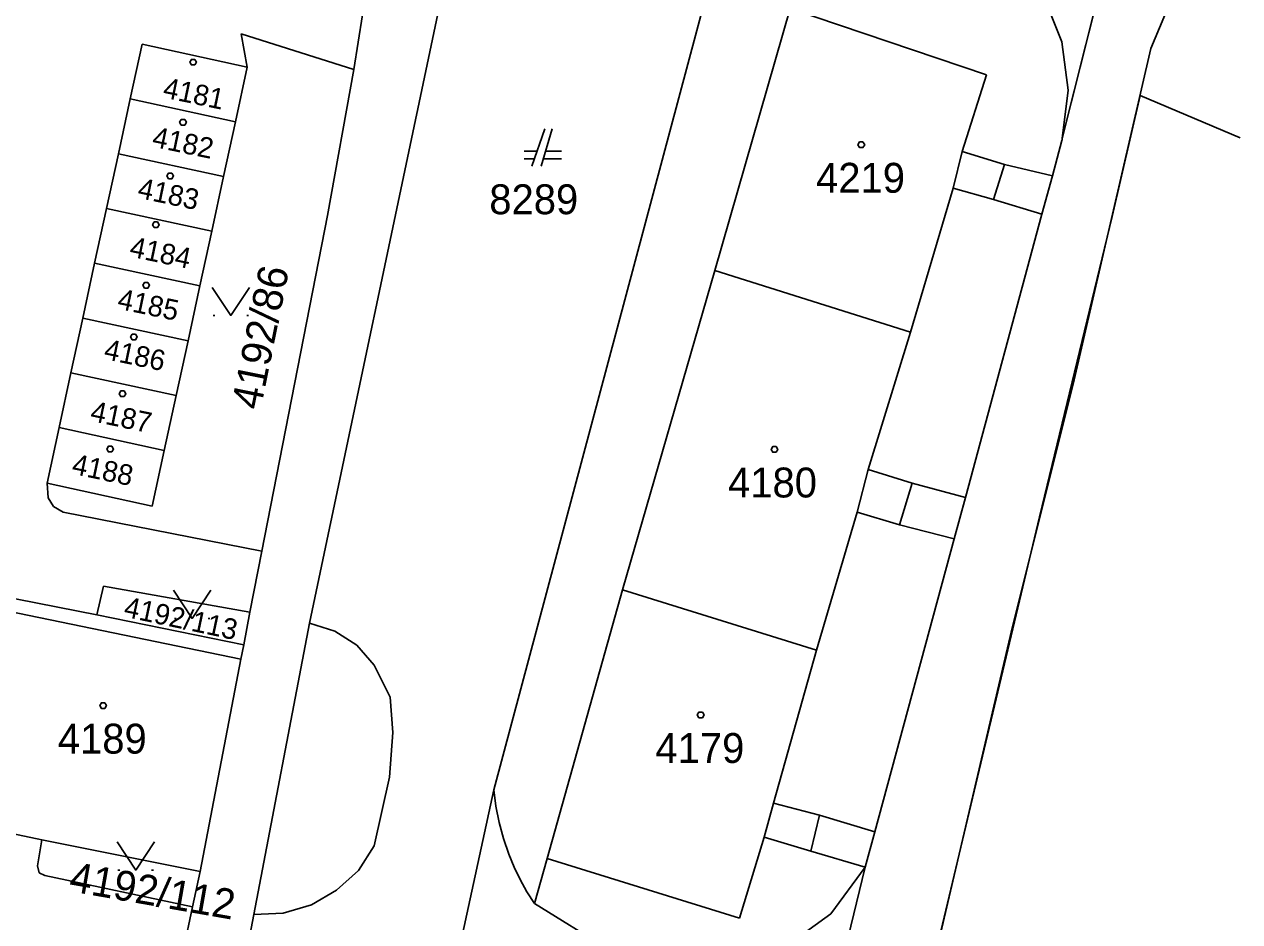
# Model space of a CAD drawing. Extents: x -263587 to -261993, y -1238795 to -1236748.
# Drawn here: x -262886.4 to -262821.3, y -1237709.3 to -1237661.2 of the extents above; entities that cross this region are included whole.
import ezdxf

# ---------------------------------------------------------------- set-up
doc = ezdxf.new("R2010")
doc.units = 0
doc.layers.add('Vrstva 1', color=7, linetype='Continuous')
doc.layers.add('Vrstva 2', color=7, linetype='Continuous')

msp = doc.modelspace()

# ---------------------------------------------------------------- linework, layer by layer
at = {"layer": 'Vrstva 1'}
for p, q in [((-262827.27, -1237653.08), (-262830.83, -1237667.35)), ((-262830.83, -1237667.35), (-262827.27, -1237653.08)), ((-262824.33, -1237658.31), (-262826.09, -1237662.53)), ((-262826.09, -1237662.53), (-262824.33, -1237658.31)), ((-262861.26, -1237702.2), (-262849.76, -1237659.19)), ((-262830.86, -1237662.17), (-262831.82, -1237659.75)), ((-262849.43, -1237674.41), (-262845.39, -1237660.38)), ((-262845.39, -1237660.38), (-262849.43, -1237674.41)), ((-262845.39, -1237660.38), (-262834.89, -1237663.94)), ((-262834.89, -1237663.94), (-262845.39, -1237660.38)), ((-262871.13, -1237693.29), (-262864.25, -1237660.67)), ((-262868.29, -1237660.73), (-262868.76, -1237663.65)), ((-262868.76, -1237663.65), (-262868.29, -1237660.73)), ((-262874.46, -1237663.52), (-262874.79, -1237661.74)), ((-262874.79, -1237661.74), (-262868.76, -1237663.65)), ((-262868.76, -1237663.65), (-262874.79, -1237661.74)), ((-262874.79, -1237661.74), (-262874.46, -1237663.52)), ((-262880.72, -1237665.23), (-262880.09, -1237662.3)), ((-262880.09, -1237662.3), (-262880.72, -1237665.23)), ((-262880.09, -1237662.3), (-262874.46, -1237663.52)), ((-262874.46, -1237663.52), (-262880.09, -1237662.3)), ((-262830.51, -1237664.76), (-262830.86, -1237662.17)), ((-262826.09, -1237662.53), (-262830.25, -1237680.5)), ((-262830.25, -1237680.5), (-262826.09, -1237662.53)), ((-262874.46, -1237663.52), (-262875.09, -1237666.45)), ((-262875.09, -1237666.45), (-262874.46, -1237663.52)), ((-262868.76, -1237663.65), (-262870.17, -1237671.47)), ((-262870.17, -1237671.47), (-262868.76, -1237663.65)), ((-262834.89, -1237663.94), (-262836.19, -1237668.04)), ((-262836.19, -1237668.04), (-262834.89, -1237663.94)), ((-262830.83, -1237667.35), (-262830.51, -1237664.76)), ((-262881.36, -1237668.16), (-262880.72, -1237665.23)), ((-262880.72, -1237665.23), (-262881.36, -1237668.16)), ((-262880.72, -1237665.23), (-262875.09, -1237666.45)), ((-262875.09, -1237666.45), (-262880.72, -1237665.23)), ((-262875.09, -1237666.45), (-262875.73, -1237669.38)), ((-262875.73, -1237669.38), (-262875.09, -1237666.45)), ((-262858.53, -1237666.83), (-262859.23, -1237668.83)), ((-262858.73, -1237668.83), (-262858.13, -1237666.83)), ((-262830.85, -1237667.46), (-262831.36, -1237669.34)), ((-262831.36, -1237669.34), (-262830.85, -1237667.46)), ((-262830.84, -1237667.41), (-262830.85, -1237667.46)), ((-262830.85, -1237667.46), (-262830.84, -1237667.41)), ((-262830.85, -1237667.46), (-262830.84, -1237667.41)), ((-262830.83, -1237667.35), (-262830.84, -1237667.41)), ((-262830.84, -1237667.41), (-262830.83, -1237667.35)), ((-262881.99, -1237671.09), (-262881.36, -1237668.16)), ((-262881.36, -1237668.16), (-262881.99, -1237671.09)), ((-262881.36, -1237668.16), (-262875.73, -1237669.38)), ((-262875.73, -1237669.38), (-262881.36, -1237668.16)), ((-262858.95, -1237668.03), (-262859.63, -1237668.03)), ((-262857.63, -1237668.03), (-262858.49, -1237668.03)), ((-262836.19, -1237668.04), (-262836.68, -1237670)), ((-262836.19, -1237668.04), (-262833.92, -1237668.73)), ((-262833.92, -1237668.73), (-262836.19, -1237668.04)), ((-262859.63, -1237668.43), (-262859.09, -1237668.43)), ((-262858.61, -1237668.43), (-262857.63, -1237668.43)), ((-262833.92, -1237668.73), (-262834.51, -1237670.62)), ((-262834.51, -1237670.62), (-262833.92, -1237668.73)), ((-262833.92, -1237668.73), (-262831.36, -1237669.34)), ((-262875.73, -1237669.38), (-262876.36, -1237672.31)), ((-262876.36, -1237672.31), (-262875.73, -1237669.38)), ((-262831.36, -1237669.34), (-262831.92, -1237671.4)), ((-262831.92, -1237671.4), (-262831.36, -1237669.34)), ((-262836.68, -1237670), (-262838.95, -1237677.71)), ((-262838.95, -1237677.71), (-262836.68, -1237670)), ((-262834.51, -1237670.62), (-262836.68, -1237670)), ((-262836.68, -1237670), (-262834.51, -1237670.62)), ((-262834.51, -1237670.62), (-262831.92, -1237671.4)), ((-262882.63, -1237674.02), (-262881.99, -1237671.09)), ((-262881.99, -1237671.09), (-262882.63, -1237674.02)), ((-262881.99, -1237671.09), (-262876.36, -1237672.31)), ((-262876.36, -1237672.31), (-262881.99, -1237671.09)), ((-262870.17, -1237671.47), (-262873.68, -1237689.44)), ((-262873.68, -1237689.44), (-262870.17, -1237671.47)), ((-262831.92, -1237671.4), (-262836.01, -1237686.56)), ((-262836.01, -1237686.56), (-262831.92, -1237671.4)), ((-262876.36, -1237672.31), (-262877, -1237675.24)), ((-262877, -1237675.24), (-262876.36, -1237672.31)), ((-262883.26, -1237676.96), (-262882.63, -1237674.02)), ((-262882.63, -1237674.02), (-262883.26, -1237676.96)), ((-262882.63, -1237674.02), (-262877, -1237675.24)), ((-262877, -1237675.24), (-262882.63, -1237674.02)), ((-262854.38, -1237691.5), (-262849.43, -1237674.41)), ((-262849.43, -1237674.41), (-262854.38, -1237691.5)), ((-262849.43, -1237674.41), (-262838.95, -1237677.71)), ((-262838.95, -1237677.71), (-262849.43, -1237674.41)), ((-262877, -1237675.24), (-262877.63, -1237678.18)), ((-262877.63, -1237678.18), (-262877, -1237675.24)), ((-262883.9, -1237679.89), (-262883.26, -1237676.96)), ((-262883.26, -1237676.96), (-262883.9, -1237679.89)), ((-262883.26, -1237676.96), (-262877.63, -1237678.18)), ((-262877.63, -1237678.18), (-262883.26, -1237676.96)), ((-262876.29, -1237676.82), (-262876.19, -1237676.82)), ((-262874.49, -1237676.82), (-262874.39, -1237676.82)), ((-262838.95, -1237677.71), (-262841.22, -1237685.07)), ((-262841.22, -1237685.07), (-262838.95, -1237677.71)), ((-262877.63, -1237678.18), (-262878.27, -1237681.11)), ((-262878.27, -1237681.11), (-262877.63, -1237678.18)), ((-262884.53, -1237682.82), (-262883.9, -1237679.89)), ((-262883.9, -1237679.89), (-262884.53, -1237682.82)), ((-262878.27, -1237681.11), (-262883.9, -1237679.89)), ((-262883.9, -1237679.89), (-262878.27, -1237681.11)), ((-262830.25, -1237680.5), (-262833.5, -1237693.46)), ((-262833.5, -1237693.46), (-262830.25, -1237680.5)), ((-262878.27, -1237681.11), (-262878.9, -1237684.04)), ((-262878.9, -1237684.04), (-262878.27, -1237681.11)), ((-262885.18, -1237685.8), (-262884.53, -1237682.82)), ((-262884.53, -1237682.82), (-262885.18, -1237685.8)), ((-262878.9, -1237684.04), (-262884.53, -1237682.82)), ((-262884.53, -1237682.82), (-262878.9, -1237684.04)), ((-262878.9, -1237684.04), (-262879.55, -1237687.02)), ((-262879.55, -1237687.02), (-262878.9, -1237684.04)), ((-262841.22, -1237685.07), (-262841.81, -1237687.35)), ((-262841.22, -1237685.07), (-262838.87, -1237685.79)), ((-262838.87, -1237685.79), (-262841.22, -1237685.07)), ((-262879.55, -1237687.02), (-262885.18, -1237685.8)), ((-262885.18, -1237685.8), (-262879.55, -1237687.02)), ((-262885.11, -1237686.58), (-262885.18, -1237685.8)), ((-262885.18, -1237685.8), (-262885.11, -1237686.58)), ((-262838.87, -1237685.79), (-262839.55, -1237688.03)), ((-262839.55, -1237688.03), (-262838.87, -1237685.79)), ((-262838.87, -1237685.79), (-262836.01, -1237686.56)), ((-262884.83, -1237687.04), (-262885.11, -1237686.58)), ((-262885.11, -1237686.58), (-262884.83, -1237687.04)), ((-262884.31, -1237687.35), (-262884.83, -1237687.04)), ((-262884.83, -1237687.04), (-262884.31, -1237687.35)), ((-262836.01, -1237686.56), (-262836.62, -1237688.77)), ((-262836.62, -1237688.77), (-262836.01, -1237686.56)), ((-262873.68, -1237689.44), (-262884.31, -1237687.35)), ((-262884.31, -1237687.35), (-262873.68, -1237689.44)), ((-262841.81, -1237687.35), (-262843.98, -1237694.73)), ((-262843.98, -1237694.73), (-262841.81, -1237687.35)), ((-262839.55, -1237688.03), (-262841.81, -1237687.35)), ((-262841.81, -1237687.35), (-262839.55, -1237688.03)), ((-262839.55, -1237688.03), (-262836.62, -1237688.77)), ((-262836.62, -1237688.77), (-262840.86, -1237704.45)), ((-262840.86, -1237704.45), (-262836.62, -1237688.77)), ((-262873.68, -1237689.44), (-262874.32, -1237692.7)), ((-262874.32, -1237692.7), (-262873.68, -1237689.44)), ((-262882.52, -1237692.85), (-262889.58, -1237691.44)), ((-262889.58, -1237691.44), (-262882.52, -1237692.85)), ((-262882.16, -1237691.3), (-262882.52, -1237692.85)), ((-262882.52, -1237692.85), (-262882.16, -1237691.3)), ((-262874.32, -1237692.7), (-262882.16, -1237691.3)), ((-262882.16, -1237691.3), (-262874.32, -1237692.7)), ((-262858.4, -1237705.89), (-262854.38, -1237691.5)), ((-262854.38, -1237691.5), (-262858.4, -1237705.89)), ((-262843.98, -1237694.73), (-262854.38, -1237691.5)), ((-262854.38, -1237691.5), (-262843.98, -1237694.73)), ((-262889.71, -1237692.15), (-262874.81, -1237695.21)), ((-262874.65, -1237694.44), (-262882.52, -1237692.85)), ((-262882.52, -1237692.85), (-262874.65, -1237694.44)), ((-262874.32, -1237692.7), (-262874.65, -1237694.44)), ((-262874.65, -1237694.44), (-262874.32, -1237692.7)), ((-262878.36, -1237693.03), (-262878.26, -1237693.03)), ((-262876.56, -1237693.03), (-262876.46, -1237693.03)), ((-262874.1, -1237708.88), (-262871.13, -1237693.29)), ((-262871.13, -1237693.29), (-262869.78, -1237693.71)), ((-262833.5, -1237693.46), (-262838.43, -1237714.48)), ((-262838.43, -1237714.48), (-262833.5, -1237693.46)), ((-262869.78, -1237693.71), (-262868.59, -1237694.47)), ((-262874.65, -1237694.44), (-262874.81, -1237695.21)), ((-262874.81, -1237695.21), (-262874.65, -1237694.44)), ((-262868.59, -1237694.47), (-262867.66, -1237695.53)), ((-262843.98, -1237694.73), (-262846.29, -1237702.92)), ((-262846.29, -1237702.92), (-262843.98, -1237694.73)), ((-262874.81, -1237695.21), (-262876.99, -1237706.58)), ((-262876.99, -1237706.58), (-262874.81, -1237695.21)), ((-262867.66, -1237695.53), (-262866.81, -1237697.24)), ((-262866.81, -1237697.24), (-262866.67, -1237699.14)), ((-262866.67, -1237699.14), (-262866.84, -1237701.53)), ((-262866.84, -1237701.53), (-262867.66, -1237705.21)), ((-262864.55, -1237717.39), (-262861.26, -1237702.2)), ((-262861.26, -1237702.2), (-262864.55, -1237717.39)), ((-262861.26, -1237702.2), (-262861.15, -1237703.08)), ((-262861.15, -1237703.08), (-262861.26, -1237702.2)), ((-262861.15, -1237703.08), (-262860.98, -1237703.96)), ((-262860.98, -1237703.96), (-262861.15, -1237703.08)), ((-262846.29, -1237702.92), (-262846.79, -1237704.74)), ((-262846.29, -1237702.92), (-262843.82, -1237703.56)), ((-262843.82, -1237703.56), (-262846.29, -1237702.92)), ((-262860.98, -1237703.96), (-262860.75, -1237704.82)), ((-262860.75, -1237704.82), (-262860.98, -1237703.96)), ((-262843.82, -1237703.56), (-262844.29, -1237705.49)), ((-262844.29, -1237705.49), (-262843.82, -1237703.56)), ((-262843.82, -1237703.56), (-262840.86, -1237704.45)), ((-262887.07, -1237704.55), (-262885.45, -1237704.88)), ((-262885.45, -1237704.88), (-262887.07, -1237704.55)), ((-262840.86, -1237704.45), (-262841.38, -1237706.35)), ((-262841.38, -1237706.35), (-262840.86, -1237704.45)), ((-262885.45, -1237704.88), (-262885.68, -1237706.28)), ((-262885.68, -1237706.28), (-262885.45, -1237704.88)), ((-262876.99, -1237706.58), (-262885.45, -1237704.88)), ((-262885.45, -1237704.88), (-262876.99, -1237706.58)), ((-262867.66, -1237705.21), (-262868.51, -1237706.52)), ((-262860.75, -1237704.82), (-262860.46, -1237705.66)), ((-262860.46, -1237705.66), (-262860.75, -1237704.82)), ((-262846.79, -1237704.74), (-262848.11, -1237709.07)), ((-262848.11, -1237709.07), (-262846.79, -1237704.74)), ((-262844.29, -1237705.49), (-262846.79, -1237704.74)), ((-262846.79, -1237704.74), (-262844.29, -1237705.49)), ((-262860.46, -1237705.66), (-262860.17, -1237706.35)), ((-262860.17, -1237706.35), (-262860.46, -1237705.66)), ((-262859.09, -1237708.29), (-262858.4, -1237705.89)), ((-262858.4, -1237705.89), (-262859.09, -1237708.29)), ((-262848.11, -1237709.07), (-262858.4, -1237705.89)), ((-262858.4, -1237705.89), (-262848.11, -1237709.07)), ((-262844.29, -1237705.49), (-262841.38, -1237706.35)), ((-262885.68, -1237706.28), (-262885.6, -1237706.66)), ((-262885.6, -1237706.66), (-262885.68, -1237706.28)), ((-262881.38, -1237706.5), (-262881.28, -1237706.5)), ((-262879.58, -1237706.5), (-262879.48, -1237706.5)), ((-262876.99, -1237706.58), (-262877.39, -1237708.47)), ((-262877.39, -1237708.47), (-262876.99, -1237706.58)), ((-262868.51, -1237706.52), (-262869.68, -1237707.57)), ((-262860.17, -1237706.35), (-262859.85, -1237707.01)), ((-262859.85, -1237707.01), (-262860.17, -1237706.35)), ((-262841.38, -1237706.35), (-262843.22, -1237708.84)), ((-262841.38, -1237706.35), (-262843.07, -1237713.24)), ((-262843.07, -1237713.24), (-262841.38, -1237706.35)), ((-262885.6, -1237706.66), (-262885.3, -1237706.8)), ((-262885.3, -1237706.8), (-262885.6, -1237706.66)), ((-262885.3, -1237706.8), (-262877.39, -1237708.47)), ((-262877.39, -1237708.47), (-262885.3, -1237706.8)), ((-262859.85, -1237707.01), (-262859.49, -1237707.66)), ((-262859.49, -1237707.66), (-262859.85, -1237707.01)), ((-262869.68, -1237707.57), (-262871.03, -1237708.37)), ((-262859.49, -1237707.66), (-262859.09, -1237708.29)), ((-262859.09, -1237708.29), (-262859.49, -1237707.66)), ((-262877.39, -1237708.47), (-262878.1, -1237711.83)), ((-262878.1, -1237711.83), (-262877.39, -1237708.47)), ((-262871.03, -1237708.37), (-262872.53, -1237708.81)), ((-262852.38, -1237712.43), (-262859.09, -1237708.29)), ((-262874.64, -1237711.62), (-262874.1, -1237708.88)), ((-262872.53, -1237708.81), (-262874.1, -1237708.88)), ((-262843.22, -1237708.84), (-262846.5, -1237711.2))]:
    msp.add_line(p, q, dxfattribs=at)
for points in [[(-262877.27, -1237663.11), (-262877.18, -1237663.26), (-262877.27, -1237663.41), (-262877.45, -1237663.41), (-262877.54, -1237663.26), (-262877.45, -1237663.11)], [(-262877.81, -1237666.33), (-262877.72, -1237666.48), (-262877.81, -1237666.63), (-262877.99, -1237666.63), (-262878.08, -1237666.48), (-262877.99, -1237666.33)], [(-262841.5, -1237667.53), (-262841.41, -1237667.68), (-262841.5, -1237667.83), (-262841.68, -1237667.83), (-262841.77, -1237667.68), (-262841.68, -1237667.53)], [(-262878.49, -1237669.2), (-262878.4, -1237669.35), (-262878.49, -1237669.5), (-262878.67, -1237669.5), (-262878.76, -1237669.35), (-262878.67, -1237669.2)], [(-262879.26, -1237671.81), (-262879.17, -1237671.96), (-262879.26, -1237672.11), (-262879.44, -1237672.11), (-262879.53, -1237671.96), (-262879.44, -1237671.81)], [(-262879.78, -1237675.05), (-262879.69, -1237675.2), (-262879.78, -1237675.35), (-262879.96, -1237675.35), (-262880.05, -1237675.2), (-262879.96, -1237675.05)], [(-262880.44, -1237677.82), (-262880.35, -1237677.97), (-262880.44, -1237678.12), (-262880.62, -1237678.12), (-262880.71, -1237677.97), (-262880.62, -1237677.82)], [(-262881.05, -1237680.86), (-262880.96, -1237681.01), (-262881.05, -1237681.16), (-262881.23, -1237681.16), (-262881.32, -1237681.01), (-262881.23, -1237680.86)], [(-262881.71, -1237683.82), (-262881.62, -1237683.97), (-262881.71, -1237684.12), (-262881.89, -1237684.12), (-262881.98, -1237683.97), (-262881.89, -1237683.82)], [(-262846.15, -1237683.84), (-262846.06, -1237683.99), (-262846.15, -1237684.14), (-262846.33, -1237684.14), (-262846.42, -1237683.99), (-262846.33, -1237683.84)], [(-262882.09, -1237697.55), (-262882, -1237697.7), (-262882.09, -1237697.85), (-262882.27, -1237697.85), (-262882.36, -1237697.7), (-262882.27, -1237697.55)], [(-262850.1, -1237698.05), (-262850.01, -1237698.2), (-262850.1, -1237698.35), (-262850.28, -1237698.35), (-262850.37, -1237698.2), (-262850.28, -1237698.05)]]:
    msp.add_lwpolyline(points, close=True, dxfattribs=at)
for points in [[(-262876.34, -1237675.32), (-262875.34, -1237676.82), (-262874.34, -1237675.32)], [(-262878.41, -1237691.53), (-262877.41, -1237693.03), (-262876.41, -1237691.53)], [(-262881.43, -1237705), (-262880.43, -1237706.5), (-262879.43, -1237705)]]:
    msp.add_lwpolyline(points, dxfattribs=at)
at = {"layer": 'Vrstva 2'}
msp.add_lwpolyline([(-262850.83, -1237794.01), (-262846.699, -1237756.584), (-262829.89, -1237759.64), (-262828.81, -1237754.37), (-262825.625, -1237736.36), (-262822.52, -1237718.81), (-262821.36, -1237713.08), (-262837.415, -1237710.153), (-262832.045, -1237687.595), (-262828.17, -1237671.515), (-262826.67, -1237665.04), (-262821.31, -1237667.32)], dxfattribs=at)

# ---------------------------------------------------------------- texts
at = {"layer": 'Vrstva 1'}
for s, height, rotation, p in [('4181', 1.1, 348.24375, (-262879.027, -1237665.142)), ('4182', 1.1, 348.24375, (-262879.604, -1237667.775)), ('4183', 1.1, 348.24375, (-262880.384, -1237670.515)), ('4184', 1.1, 348.24375, (-262880.814, -1237673.655)), ('4192/86', 1.6, 78.55251, (-262873.751, -1237681.927)), ('4185', 1.1, 348.24375, (-262881.464, -1237676.445)), ('4186', 1.1, 348.24375, (-262882.184, -1237679.139)), ('4187', 1.1, 348.24375, (-262882.914, -1237682.455)), ('4188', 1.1, 348.24375, (-262883.904, -1237685.285)), ('4192/113', 1.1, 348.07186, (-262881.119, -1237692.93)), ('4192/112', 1.6, 350.07721, (-262884.058, -1237707.623))]:
    msp.add_text(s, height=height, rotation=rotation, dxfattribs=at).set_placement(p)
for s, p in [('4219', (-262844.011, -1237670.25)), ('8289', (-262861.504, -1237671.4)), ('4180', (-262848.724, -1237686.56)), ('4189', (-262884.601, -1237700.27)), ('4179', (-262852.611, -1237700.77))]:
    msp.add_text(s, height=1.6, dxfattribs=at).set_placement(p)

doc.saveas('drawing.dxf')
